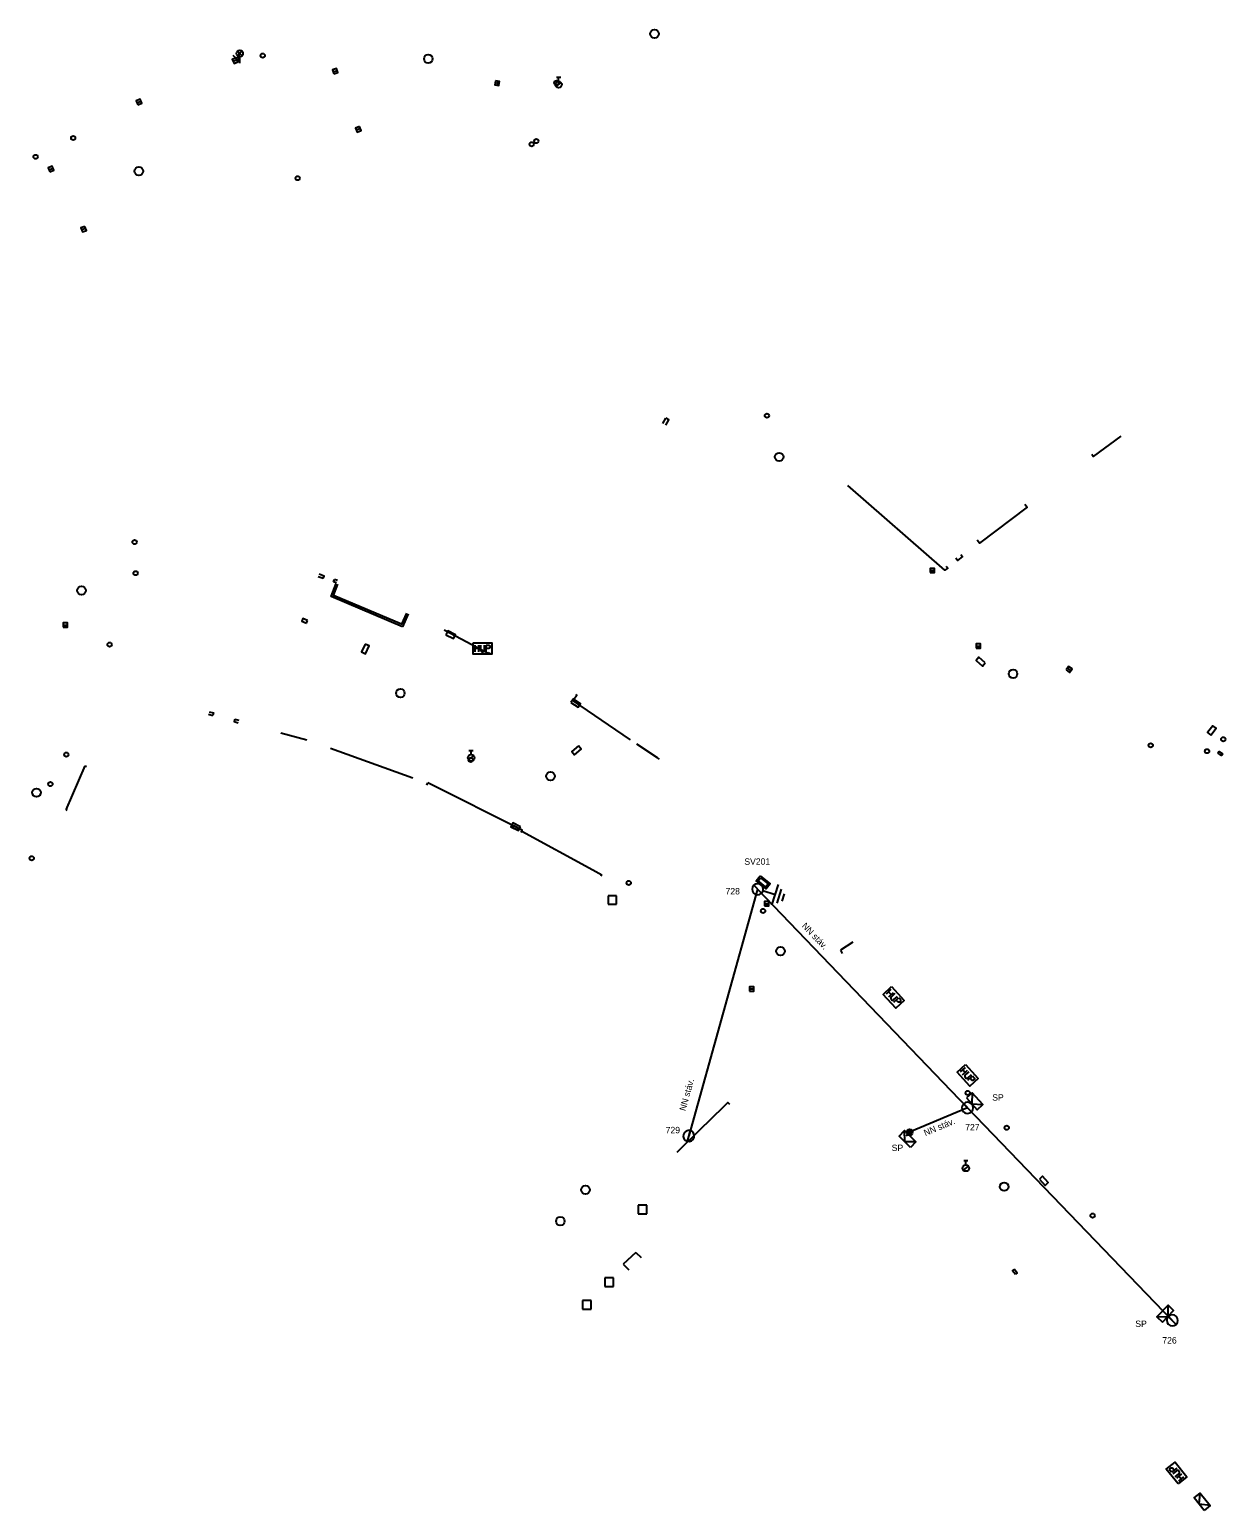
# Model space of a CAD drawing. Extents: x -584388 to -581645, y -1210859 to -1208922.
# Drawn here: x -582703.6 to -582564.2, y -1209773.8 to -1209601.3 of the extents above; entities that cross this region are included whole.
import ezdxf

# ---------------------------------------------------------------- set-up
doc = ezdxf.new("R2010")
doc.units = 0
for name, color, linetype in [('CIZÍ_NADZEM', 7, 'Continuous'), ('ELE_EON', 7, 'Continuous'), ('ELE_EON_POPIS', 7, 'Continuous')]:
    doc.layers.add(name, color=color, linetype=linetype)

msp = doc.modelspace()

# ---------------------------------------------------------------- linework, layer by layer
at = {"layer": 'CIZÍ_NADZEM'}
for p, q in [((-582679.35, -1209604.35), (-582678.83, -1209603.82)), ((-582678.82, -1209604.34), (-582679.35, -1209603.82)), ((-582679.18, -1209604.03), (-582679.21, -1209604.48)), ((-582679.53, -1209604.61), (-582679.87, -1209604.32)), ((-582679.4, -1209604.83), (-582679.86, -1209605.03)), ((-582679.09, -1209605.21), (-582679.09, -1209604.46)), ((-582668.21, -1209606.22), (-582667.73, -1209606.06)), ((-582649.04, -1209607.29), (-582649.12, -1209607.79)), ((-582642.21, -1209607.94), (-582641.62, -1209607.48)), ((-582642.17, -1209606.83), (-582641.67, -1209606.83)), ((-582641.92, -1209607.33), (-582641.92, -1209606.83)), ((-582691.08, -1209609.83), (-582690.62, -1209609.63)), ((-582665.03, -1209612.83), (-582665.49, -1209613.01)), ((-582701.33, -1209617.62), (-582700.85, -1209617.46)), ((-582697.05, -1209624.47), (-582697.53, -1209624.63)), ((-582598.59, -1209664.32), (-582598.09, -1209664.32)), ((-582699.66, -1209670.68), (-582699.16, -1209670.68)), ((-582593.23, -1209673.13), (-582592.73, -1209673.13)), ((-582582.62, -1209675.69), (-582582.22, -1209675.99)), ((-582652.37, -1209685.28), (-582651.87, -1209685.28)), ((-582652.12, -1209685.78), (-582652.12, -1209685.28)), ((-582652.41, -1209686.38), (-582651.82, -1209685.92)), ((-582635.16, -1209702.21), (-582636.16, -1209702.21)), ((-582636.16, -1209702.21), (-582636.16, -1209703.21)), ((-582635.16, -1209703.21), (-582635.16, -1209702.21)), ((-582636.16, -1209703.21), (-582635.16, -1209703.21)), ((-582617.91, -1209703.15), (-582617.41, -1209703.15)), ((-582619.65, -1209713.07), (-582619.15, -1209713.07)), ((-582594.7, -1209733.06), (-582594.2, -1209733.06)), ((-582594.45, -1209733.56), (-582594.45, -1209733.06)), ((-582594.74, -1209734.17), (-582594.15, -1209733.71)), ((-582631.64, -1209738.27), (-582632.64, -1209738.27)), ((-582632.64, -1209738.27), (-582632.64, -1209739.27)), ((-582631.64, -1209739.27), (-582631.64, -1209738.27)), ((-582632.64, -1209739.27), (-582631.64, -1209739.27)), ((-582635.52, -1209746.74), (-582636.52, -1209746.74)), ((-582636.52, -1209746.74), (-582636.52, -1209747.74)), ((-582635.52, -1209747.74), (-582635.52, -1209746.74)), ((-582636.52, -1209747.74), (-582635.52, -1209747.74)), ((-582638.14, -1209749.38), (-582639.14, -1209749.38)), ((-582639.14, -1209749.38), (-582639.14, -1209750.38)), ((-582639.14, -1209750.38), (-582638.14, -1209750.38)), ((-582638.14, -1209750.38), (-582638.14, -1209749.38))]:
    msp.add_line(p, q, dxfattribs=at)
for points in [[(-582679.5, -1209604.6), (-582679.96, -1209604.8), (-582679.76, -1209605.26), (-582679.3, -1209605.06)], [(-582679.21, -1209604.48), (-582679.24, -1209604.87), (-582679.53, -1209604.61)], [(-582668.12, -1209606.46), (-582667.65, -1209606.29), (-582667.82, -1209605.82), (-582668.29, -1209605.99)], [(-582649.29, -1209607.26), (-582649.36, -1209607.75), (-582648.87, -1209607.82), (-582648.8, -1209607.33)], [(-582690.98, -1209610.06), (-582690.52, -1209609.86), (-582690.72, -1209609.4), (-582691.18, -1209609.6)], [(-582665.12, -1209612.6), (-582665.58, -1209612.78), (-582665.4, -1209613.24), (-582664.94, -1209613.06)], [(-582701.24, -1209617.86), (-582700.77, -1209617.69), (-582700.94, -1209617.22), (-582701.41, -1209617.39)], [(-582697.14, -1209624.23), (-582697.61, -1209624.4), (-582697.44, -1209624.87), (-582696.97, -1209624.7)], [(-582598.59, -1209664.57), (-582598.09, -1209664.57), (-582598.09, -1209664.07), (-582598.59, -1209664.07)], [(-582699.66, -1209670.93), (-582699.16, -1209670.93), (-582699.16, -1209670.43), (-582699.66, -1209670.43)], [(-582655.08, -1209671.8), (-582654.19, -1209672.26), (-582653.96, -1209671.82), (-582654.85, -1209671.36)], [(-582664.48, -1209672.9), (-582664.9, -1209673.81), (-582664.44, -1209674.02), (-582664.02, -1209673.11)], [(-582593.23, -1209673.38), (-582592.73, -1209673.38), (-582592.73, -1209672.88), (-582593.23, -1209672.88)], [(-582592.18, -1209675.09), (-582592.93, -1209674.43), (-582593.26, -1209674.81), (-582592.51, -1209675.47)], [(-582582.77, -1209675.9), (-582582.36, -1209676.19), (-582582.07, -1209675.78), (-582582.48, -1209675.49)], [(-582640.48, -1209679.7), (-582639.64, -1209680.24), (-582639.36, -1209679.82), (-582640.2, -1209679.28)], [(-582565.87, -1209683.5), (-582565.26, -1209682.7), (-582565.65, -1209682.4), (-582566.26, -1209683.2)], [(-582639.62, -1209684.76), (-582640.38, -1209685.4), (-582640.06, -1209685.78), (-582639.3, -1209685.14)], [(-582646.37, -1209694.17), (-582647.27, -1209693.72), (-582647.49, -1209694.17), (-582646.59, -1209694.62)], [(-582617.91, -1209703.4), (-582617.41, -1209703.4), (-582617.41, -1209702.9), (-582617.91, -1209702.9)], [(-582619.65, -1209713.32), (-582619.15, -1209713.32), (-582619.15, -1209712.82), (-582619.65, -1209712.82)], [(-582585.88, -1209735.23), (-582585.2, -1209735.97), (-582584.84, -1209735.63), (-582585.52, -1209734.89)]]:
    msp.add_lwpolyline(points, close=True, dxfattribs=at)
for points in [[(-582629.77, -1209647.21), (-582629.41, -1209646.58)], [(-582629.44, -1209647.4), (-582629.08, -1209646.76), (-582629.41, -1209646.58)], [(-582576.39, -1209648.66), (-582579.59, -1209651.05), (-582579.68, -1209650.93), (-582579.77, -1209650.81)], [(-582596.74, -1209663.8), (-582596.56, -1209664.04), (-582596.88, -1209664.29), (-582608.22, -1209654.4)], [(-582587.57, -1209656.59), (-582587.3, -1209656.95), (-582592.84, -1209661.14), (-582593.11, -1209660.78)], [(-582595.03, -1209662.45), (-582594.84, -1209662.69), (-582595.43, -1209663.14), (-582595.61, -1209662.9)], [(-582669.36, -1209665.24), (-582669.95, -1209665.04)], [(-582669.36, -1209665.24), (-582669.26, -1209664.96), (-582669.84, -1209664.76)], [(-582660.11, -1209670.88), (-582668.43, -1209667.36), (-582667.86, -1209665.82)], [(-582668.15, -1209665.64), (-582668.05, -1209665.36)], [(-582667.83, -1209665.75), (-582668.15, -1209665.64)], [(-582659.64, -1209669.28), (-582660.22, -1209670.59), (-582668.15, -1209667.24), (-582667.65, -1209665.9)], [(-582667.71, -1209665.47), (-582668.05, -1209665.36)], [(-582659.44, -1209669.37), (-582660.11, -1209670.88)], [(-582671.19, -1209670.14), (-582671.73, -1209669.91), (-582671.85, -1209670.23), (-582671.31, -1209670.46)], [(-582671.31, -1209670.46), (-582671.19, -1209670.14)], [(-582650.05, -1209674.01), (-582655.27, -1209671.27)], [(-582651.89, -1209672.74), (-582649.69, -1209672.74), (-582649.69, -1209674.06), (-582651.89, -1209674.06), (-582651.89, -1209672.74)], [(-582651.67, -1209673.02), (-582651.67, -1209673.79)], [(-582651.23, -1209673.79), (-582651.23, -1209673.02)], [(-582651.01, -1209673.02), (-582651.01, -1209673.57), (-582650.98, -1209673.68), (-582650.91, -1209673.75), (-582650.82, -1209673.79), (-582650.76, -1209673.79), (-582650.66, -1209673.75), (-582650.6, -1209673.68), (-582650.57, -1209673.57), (-582650.57, -1209673.02)], [(-582650.35, -1209673.02), (-582650.06, -1209673.02), (-582649.97, -1209673.05), (-582649.94, -1209673.09), (-582649.91, -1209673.16), (-582649.91, -1209673.27), (-582649.94, -1209673.34), (-582649.97, -1209673.38), (-582650.06, -1209673.42), (-582650.35, -1209673.42)], [(-582650.35, -1209673.79), (-582650.35, -1209673.02)], [(-582651.67, -1209673.38), (-582651.23, -1209673.38)], [(-582650.05, -1209674.01), (-582649.96, -1209673.83)], [(-582633.55, -1209684.03), (-582640.27, -1209679.46), (-582639.8, -1209678.83), (-582639.9, -1209678.75)], [(-582682.72, -1209681.07), (-582682.24, -1209681.21)], [(-582682.64, -1209680.78), (-582682.16, -1209680.92), (-582682.24, -1209681.21)], [(-582679.66, -1209681.63), (-582679.74, -1209681.92), (-582679.27, -1209682.06)], [(-582679.66, -1209681.63), (-582679.18, -1209681.77)], [(-582674.29, -1209683.24), (-582671.27, -1209684.05)], [(-582668.53, -1209685.03), (-582658.93, -1209688.46)], [(-582630.4, -1209686.14), (-582632.8, -1209684.55)], [(-582699.34, -1209692.2), (-582697.1, -1209687.08)], [(-582697.1, -1209687.08), (-582696.96, -1209687.14)], [(-582630.15, -1209686.31), (-582630.4, -1209686.14)], [(-582564.85, -1209685.75), (-582565.05, -1209685.62), (-582564.91, -1209685.41), (-582564.52, -1209685.67), (-582564.65, -1209685.88), (-582564.85, -1209685.75)], [(-582657.3, -1209689.34), (-582657.17, -1209689.07)], [(-582646.21, -1209694.69), (-582646.15, -1209694.56), (-582657.17, -1209689.07)], [(-582699.34, -1209692.2), (-582699.2, -1209692.26)], [(-582647.27, -1209694.26), (-582647.16, -1209694.04), (-582646.68, -1209694.29)], [(-582647.27, -1209694.26), (-582646.79, -1209694.51), (-582646.68, -1209694.29)], [(-582646.21, -1209694.69), (-582646.33, -1209694.86)], [(-582646.21, -1209694.69), (-582637.92, -1209699.2)], [(-582637.92, -1209699.2), (-582636.89, -1209699.76)], [(-582636.89, -1209699.76), (-582636.99, -1209699.93)], [(-582607.61, -1209707.64), (-582609.06, -1209708.54)], [(-582609.06, -1209708.54), (-582608.86, -1209708.94)], [(-582603.13, -1209712.79), (-582601.62, -1209714.4), (-582602.59, -1209715.3), (-582604.09, -1209713.7), (-582603.13, -1209712.79)], [(-582603.18, -1209713.14), (-582603.74, -1209713.67)], [(-582603.45, -1209713.39), (-582603.14, -1209713.71)], [(-582603.44, -1209713.99), (-582602.88, -1209713.47)], [(-582602.73, -1209713.62), (-582603.13, -1209714), (-582603.19, -1209714.1), (-582603.2, -1209714.2), (-582603.16, -1209714.29), (-582603.12, -1209714.34), (-582603.02, -1209714.38), (-582602.93, -1209714.38), (-582602.83, -1209714.32), (-582602.43, -1209713.95)], [(-582602.84, -1209714.63), (-582602.28, -1209714.11)], [(-582602.28, -1209714.11), (-582602.08, -1209714.31), (-582602.05, -1209714.41), (-582602.05, -1209714.46), (-582602.08, -1209714.53), (-582602.16, -1209714.6), (-582602.23, -1209714.63), (-582602.28, -1209714.63), (-582602.37, -1209714.59), (-582602.57, -1209714.38)], [(-582594.48, -1209721.87), (-582593.01, -1209723.51), (-582594, -1209724.39), (-582595.46, -1209722.75), (-582594.48, -1209721.87)], [(-582594.54, -1209722.22), (-582595.11, -1209722.73)], [(-582594.82, -1209723.06), (-582594.24, -1209722.55)], [(-582594.81, -1209722.46), (-582594.51, -1209722.79)], [(-582594.1, -1209722.71), (-582594.51, -1209723.08), (-582594.57, -1209723.17), (-582594.58, -1209723.27), (-582594.54, -1209723.37), (-582594.5, -1209723.41), (-582594.41, -1209723.46), (-582594.32, -1209723.46), (-582594.21, -1209723.41), (-582593.8, -1209723.04)], [(-582594.23, -1209723.71), (-582593.66, -1209723.2)], [(-582593.66, -1209723.2), (-582593.47, -1209723.41), (-582593.43, -1209723.51), (-582593.44, -1209723.55), (-582593.47, -1209723.63), (-582593.55, -1209723.7), (-582593.63, -1209723.72), (-582593.68, -1209723.72), (-582593.77, -1209723.68), (-582593.96, -1209723.47)], [(-582625.48, -1209729.52), (-582622.65, -1209726.75)], [(-582622.65, -1209726.75), (-582622.19, -1209726.3), (-582621.98, -1209726.51)], [(-582628.1, -1209732.08), (-582625.48, -1209729.52)], [(-582632.91, -1209743.77), (-582634.4, -1209745.15)], [(-582632.91, -1209743.77), (-582632.31, -1209744.35)], [(-582634.4, -1209745.15), (-582633.72, -1209745.81)], [(-582588.79, -1209745.73), (-582588.99, -1209745.88), (-582588.65, -1209746.31)], [(-582588.79, -1209745.73), (-582588.45, -1209746.16), (-582588.65, -1209746.31)], [(-582569.71, -1209770.75), (-582571.09, -1209769.04), (-582570.06, -1209768.21), (-582568.68, -1209769.93), (-582569.71, -1209770.75)], [(-582570.46, -1209769.38), (-582570.64, -1209769.16), (-582570.67, -1209769.06), (-582570.66, -1209769.02), (-582570.62, -1209768.95), (-582570.54, -1209768.88), (-582570.46, -1209768.86), (-582570.41, -1209768.86), (-582570.33, -1209768.91), (-582570.15, -1209769.13)], [(-582569.86, -1209768.9), (-582570.46, -1209769.38)], [(-582570.05, -1209769.9), (-582569.62, -1209769.55), (-582569.55, -1209769.46), (-582569.54, -1209769.36), (-582569.57, -1209769.26), (-582569.61, -1209769.22), (-582569.69, -1209769.17), (-582569.79, -1209769.16), (-582569.89, -1209769.21), (-582570.32, -1209769.55)], [(-582569.31, -1209769.58), (-582569.91, -1209770.07)], [(-582569.35, -1209770.18), (-582569.63, -1209769.84)], [(-582569.63, -1209770.41), (-582569.03, -1209769.93)]]:
    msp.add_lwpolyline(points, dxfattribs=at)
for centre, radius in [((-582630.74, -1209601.8), 0.5), ((-582679.09, -1209604.08), 0.375), ((-582676.41, -1209604.33), 0.25), ((-582657.11, -1209604.71), 0.5), ((-582642.18, -1209607.49), 0.25), ((-582641.92, -1209607.71), 0.375), ((-582698.51, -1209613.93), 0.25), ((-582645.06, -1209614.65), 0.25), ((-582644.52, -1209614.29), 0.25), ((-582702.89, -1209616.12), 0.25), ((-582690.86, -1209617.8), 0.5), ((-582672.34, -1209618.61), 0.25), ((-582617.64, -1209646.28), 0.25), ((-582616.21, -1209651.09), 0.5), ((-582691.35, -1209661.01), 0.25), ((-582691.24, -1209664.63), 0.25), ((-582697.53, -1209666.65), 0.5), ((-582694.27, -1209672.95), 0.25), ((-582588.95, -1209676.35), 0.5), ((-582660.37, -1209678.61), 0.5), ((-582572.89, -1209684.69), 0.25), ((-582566.33, -1209685.37), 0.25), ((-582564.44, -1209683.98), 0.25), ((-582699.31, -1209685.76), 0.25), ((-582652.12, -1209686.15), 0.375), ((-582652.17, -1209686.39), 0.25), ((-582642.87, -1209688.28), 0.5), ((-582702.79, -1209690.2), 0.5), ((-582701.16, -1209689.2), 0.25), ((-582703.34, -1209697.84), 0.25), ((-582633.75, -1209700.72), 0.25), ((-582618.08, -1209703.98), 0.25), ((-582616.05, -1209708.66), 0.5), ((-582594.22, -1209725.18), 0.25), ((-582589.68, -1209729.24), 0.25), ((-582594.45, -1209733.94), 0.375), ((-582638.78, -1209736.48), 0.5), ((-582589.98, -1209736.11), 0.5), ((-582641.72, -1209740.14), 0.5), ((-582579.68, -1209739.47), 0.25)]:
    msp.add_circle(centre, radius, dxfattribs=at)
at = {"layer": 'ELE_EON'}
for p, q in [((-582618.27, -1209701.93), (-582619.17, -1209700.99)), ((-582616.67, -1209702.11), (-582618.1, -1209701.66)), ((-582617.05, -1209703.3), (-582616.29, -1209700.92)), ((-582616.45, -1209703.07), (-582615.94, -1209701.45)), ((-582615.85, -1209702.84), (-582615.58, -1209701.98)), ((-582593.8, -1209727.39), (-582594.7, -1209726.45)), ((-582626.58, -1209729.56), (-582626.92, -1209730.82)), ((-582601.25, -1209730.03), (-582601.41, -1209730.21)), ((-582569.93, -1209752.16), (-582570.83, -1209751.22))]:
    msp.add_line(p, q, dxfattribs=at)
for points in [[(-582618.44, -1209699.9), (-582617.26, -1209700.83), (-582617.73, -1209701.42), (-582618.9, -1209700.48)], [(-582618.37, -1209700.14), (-582617.51, -1209700.82), (-582617.79, -1209701.18), (-582618.65, -1209700.49)], [(-582594.37, -1209725.77), (-582593.12, -1209727.16), (-582592.45, -1209726.55), (-582593.7, -1209725.16)], [(-582600.88, -1209731.53), (-582602.23, -1209730.22), (-582601.6, -1209729.58), (-582600.26, -1209730.88)], [(-582571.52, -1209751.9), (-582570.23, -1209750.54), (-582570.88, -1209749.92), (-582572.17, -1209751.27)], [(-582566.67, -1209773.82), (-582567.85, -1209772.36), (-582567.15, -1209771.8), (-582565.97, -1209773.26)]]:
    msp.add_lwpolyline(points, close=True, dxfattribs=at)
for points in [[(-582618.72, -1209701.46), (-582626.75, -1209730.19)], [(-582570.38, -1209751.69), (-582594.25, -1209726.92), (-582618.72, -1209701.46)], [(-582593.7, -1209725.16), (-582593.74, -1209726.46), (-582592.45, -1209726.55)], [(-582594.25, -1209726.92), (-582601.01, -1209729.77), (-582600.93, -1209730.23)], [(-582600.26, -1209730.88), (-582601.56, -1209730.88), (-582601.6, -1209729.58)], [(-582572.17, -1209751.27), (-582570.87, -1209751.22), (-582570.88, -1209749.92)], [(-582565.97, -1209773.26), (-582567.26, -1209773.09), (-582567.15, -1209771.8)]]:
    msp.add_lwpolyline(points, dxfattribs=at)
for radius in [0.35, 0.175]:
    msp.add_circle((-582601.01, -1209729.77), radius, dxfattribs=at)
for centre, start, end in [((-582618.72, -1209701.46), 313.8641, 133.8641), ((-582618.72, -1209701.46), 133.8641, 313.8641), ((-582594.25, -1209726.92), 133.94, 313.94), ((-582594.25, -1209726.92), 313.94, 133.94), ((-582626.75, -1209730.19), 74.3844, 254.3844), ((-582626.75, -1209730.19), 254.3844, 74.3844), ((-582570.38, -1209751.69), 133.6541, 313.6541), ((-582570.38, -1209751.69), 313.6541, 133.6541)]:
    msp.add_arc(centre, 0.65, start, end, dxfattribs=at)

# ---------------------------------------------------------------- texts
at = {"layer": 'ELE_EON_POPIS'}
for s, p in [('SV201', (-582620.27, -1209698.61)), ('728', (-582622.46, -1209702.06)), ('SP', (-582591.37, -1209726.09)), ('729', (-582629.44, -1209729.89)), ('727', (-582594.52, -1209729.55)), ('SP', (-582603.09, -1209731.96)), ('SP', (-582574.69, -1209752.46)), ('726', (-582571.54, -1209754.39))]:
    msp.add_text(s, height=0.75, dxfattribs=at).set_placement(p)
for rotation, p in [(313.8641, (-582613.63, -1209705.79)), (74.3844, (-582627.14, -1209727.34)), (22.8602, (-582599.16, -1209730.23))]:
    msp.add_text('NN stáv.', height=0.75, rotation=rotation, dxfattribs=at).set_placement(p)

doc.saveas('drawing.dxf')
